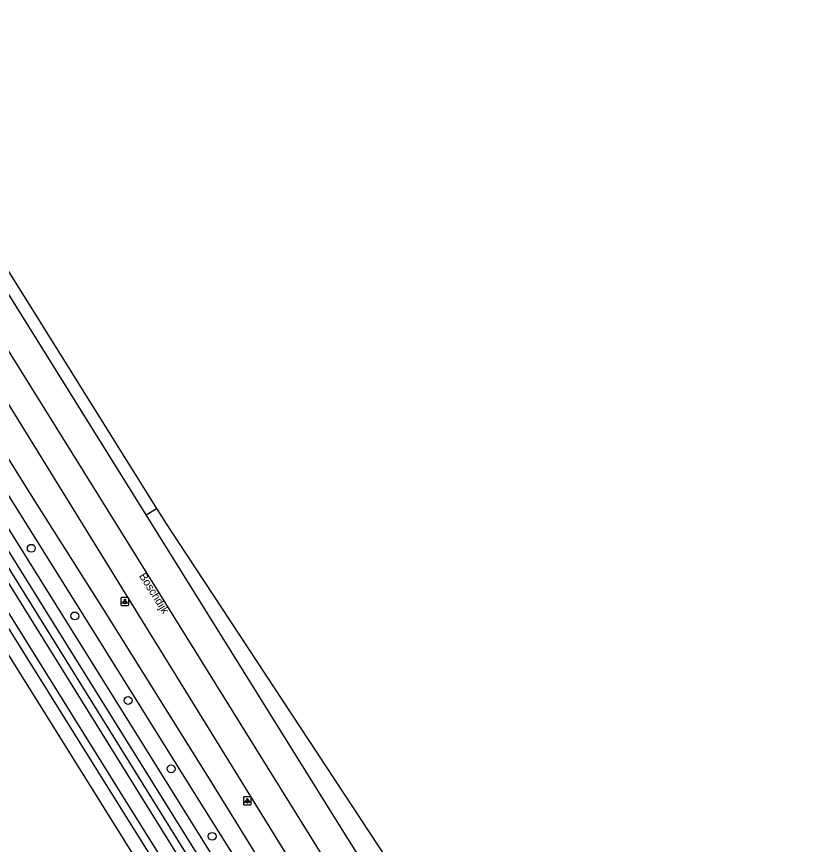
# Model space of a CAD drawing. Extents: x 158132 to 159658, y 385257 to 387209.
# Drawn here: x 159042.6 to 159140.1, y 386809.7 to 386913.1 of the extents above; entities that cross this region are included whole.
import ezdxf

# ---------------------------------------------------------------- set-up
doc = ezdxf.new("R2010")
doc.units = 0
for name, color, linetype in [('IMGEO_Boom', 7, 'Continuous'), ('IMGEO_Fietspad_gesloten', 7, 'Continuous'), ('IMGEO_Gemengd_bos', 7, 'Continuous'), ('IMGEO_Hek', 7, 'Continuous'), ('IMGEO_Lichtpunt', 7, 'Continuous'), ('IMGEO_Openbare_ruimte_label', 7, 'Continuous'), ('IMGEO_Rijbaan_regionaal_gesloten', 7, 'Continuous'), ('IMGEO_Verkeerseiland_open', 7, 'Continuous'), ('IMGEO_Voetpad_open', 7, 'Continuous'), ('IMGEO_Waterloop', 7, 'Continuous')]:
    doc.layers.add(name, color=color, linetype=linetype)

msp = doc.modelspace()

# ---------------------------------------------------------------- linework, layer by layer
at = {"layer": 'IMGEO_Boom'}
for centre in [(159044.4, 386846.72), (159049.84, 386838.27), (159056.5, 386827.71), (159061.88, 386819.16), (159067.01, 386810.74)]:
    msp.add_circle(centre, 0.489, dxfattribs=at)
at = {"layer": 'IMGEO_Fietspad_gesloten'}
for points in [[(158941.33, 387013.3), (158945.18, 387007.28), (158949.85, 387000), (158956.19, 386989.91), (158968.82, 386969.55), (158983.07, 386946.51), (158996.04, 386925.89), (159000, 386919.62), (159009.4, 386904.75), (159021.52, 386885.26), (159031.61, 386869.16), (159043.05, 386850.88), (159051.47, 386837.43), (159064.7, 386816.23), (159071.45, 386805.45), (159075.09, 386799.57), (159078.06, 386794.8)], [(159116.57, 386729), (159103.46, 386750), (159087.41, 386775.7), (159087.28, 386775.92), (159086.31, 386777.79), (159085.51, 386779.75), (159084.88, 386781.77), (159082.05, 386791.86), (159081.53, 386793.42), (159080.87, 386794.93), (159080.27, 386796.04), (159077.25, 386800.87), (159073.57, 386806.72), (159067, 386817.36), (159053.63, 386838.77), (159044.62, 386852.96), (159033.41, 386870.98), (159019.9, 386892.6), (159007.98, 386911.66), (159000, 386924.5)]]:
    msp.add_lwpolyline(points, dxfattribs=at)
at = {"layer": 'IMGEO_Gemengd_bos'}
for points in [[(158949.71, 386982.58), (158967.97, 386954.01), (158977.45, 386938.63), (158982.43, 386931.1), (158988.76, 386921.08), (159000, 386903.6), (159031.24, 386853.2), (159055.81, 386813.89), (159067.59, 386795.06), (159071.31, 386789.11), (159074.93, 386782.92), (159078.25, 386775.14), (159080.08, 386771.7)], [(159113.76, 386724.1), (159103.03, 386741.54), (159098.78, 386748.57), (159097.88, 386750), (159086.96, 386767.29), (159084.19, 386772.04), (159081.92, 386776.26), (159079.98, 386780.79), (159078.46, 386784.25), (159076.71, 386787.6), (159070.91, 386797.06), (159068.85, 386800.41), (159000, 386911.16), (158992.15, 386923.2)]]:
    msp.add_lwpolyline(points, dxfattribs=at)
at = {"layer": 'IMGEO_Hek'}
msp.add_lwpolyline([(159000, 386899.91), (159066.06, 386794.15)], dxfattribs=at)
at = {"layer": 'IMGEO_Lichtpunt'}
for p, q in [((159055.6, 386840.47), (159055.6, 386839.66)), ((159055.6, 386840.47), (159055.6, 386839.66)), ((159056.5, 386840.57), (159055.69, 386840.57)), ((159056.5, 386840.57), (159055.69, 386840.57)), ((159056.59, 386839.66), (159056.59, 386840.47)), ((159056.59, 386839.66), (159056.59, 386840.47)), ((159055.69, 386839.57), (159056.5, 386839.57)), ((159055.69, 386839.57), (159056.5, 386839.57)), ((159070.9, 386815.57), (159070.9, 386814.77)), ((159070.9, 386815.57), (159070.9, 386814.77)), ((159071.8, 386815.67), (159070.99, 386815.67)), ((159071.8, 386815.67), (159070.99, 386815.67)), ((159071.89, 386814.77), (159071.89, 386815.57)), ((159071.89, 386814.77), (159071.89, 386815.57)), ((159070.99, 386814.67), (159071.8, 386814.67)), ((159070.99, 386814.67), (159071.8, 386814.67))]:
    msp.add_line(p, q, dxfattribs=at)
for points in [[(159055.97, 386840.13), (159056.01, 386840.11), (159055.82, 386839.84), (159055.78, 386839.87), (159055.97, 386840.13)], [(159056.07, 386840.09), (159056.12, 386840.09), (159056.12, 386839.76), (159056.07, 386839.76), (159056.07, 386840.09)], [(159056.18, 386840.11), (159056.22, 386840.13), (159056.41, 386839.87), (159056.37, 386839.84), (159056.18, 386840.11)], [(159071.27, 386815.24), (159071.31, 386815.21), (159071.12, 386814.95), (159071.08, 386814.97), (159071.27, 386815.24)], [(159071.37, 386815.19), (159071.42, 386815.19), (159071.42, 386814.87), (159071.37, 386814.87), (159071.37, 386815.19)], [(159071.48, 386815.21), (159071.52, 386815.24), (159071.71, 386814.97), (159071.67, 386814.95), (159071.48, 386815.21)]]:
    msp.add_lwpolyline(points, dxfattribs=at)
for centre in [(159056.1, 386840.27), (159071.4, 386815.37)]:
    msp.add_circle(centre, 0.0994, dxfattribs=at)
for centre, start, end in [((159055.69, 386840.47), 90, 180), ((159055.69, 386840.47), 90, 180), ((159056.5, 386840.47), 0, 90), ((159056.5, 386840.47), 0, 90), ((159055.69, 386839.66), 180, 270), ((159055.69, 386839.66), 180, 270), ((159056.5, 386839.66), 270, 0), ((159056.5, 386839.66), 270, 360), ((159070.99, 386815.57), 90, 180), ((159070.99, 386815.57), 90, 180), ((159071.8, 386815.57), 0, 90), ((159071.8, 386815.57), 0, 90), ((159070.99, 386814.77), 180, 270), ((159070.99, 386814.77), 180, 270), ((159071.8, 386814.77), 270, 0), ((159071.8, 386814.77), 270, 360)]:
    msp.add_arc(centre, 0.0946, start, end, dxfattribs=at)
at = {"layer": 'IMGEO_Rijbaan_regionaal_gesloten'}
for points in [[(159132.72, 386721.99), (159125.95, 386732.99), (159118.54, 386745.29), (159113.12, 386754.13), (159106.44, 386765.8), (159097.37, 386781.66), (159076.66, 386814.97), (159052.05, 386854.56), (159019.18, 386907.28), (159008.52, 386924.33), (158987.11, 386958.55), (158967.99, 386989.3), (158948.87, 387020.05), (158922.43, 387060.66), (158915.85, 387070.53), (158892.84, 387103.79), (158867.82, 387140.66), (158850.57, 387167.06), (158841.17, 387181.88)], [(159058.74, 386850.89), (159039.3, 386882.04), (159024.03, 386906.51), (159004.62, 386937.46), (159000, 386944.85), (158989.71, 386961.33), (158975.98, 386983.29), (158965.55, 387000), (158956.04, 387014.92), (158952.62, 387020.3), (158942.06, 387036.92), (158934.41, 387048.85), (158932.01, 387052.45), (158927.86, 387058.82), (158924.52, 387063.91), (158921.65, 387068.35), (158918.5, 387073.22), (158916.22, 387076.6)], [(158937.06, 387048.69), (158937.81, 387047.54), (158938.99, 387045.64), (158941.49, 387041.35), (158949.18, 387028.98), (158954.02, 387021.18), (158956.71, 387016.86), (158965.07, 387003.5), (158967.35, 387000), (158978.52, 386982.01), (159000, 386947.66), (159016.97, 386920.42), (159031.34, 386897.46), (159040.61, 386882.82), (159060.03, 386851.7)], [(158933.03, 387037.86), (158938.97, 387028.57), (158944.43, 387020), (158946.6, 387016.58), (158951.09, 387009.51), (158957.04, 387000), (158971.62, 386976.38), (158987.66, 386950.66), (159000, 386930.88), (159006.31, 386920.77), (159012.93, 386910.23), (159024.95, 386891.53), (159076.51, 386808.08), (159079.97, 386802.5), (159097.62, 386774.07)], [(159060.03, 386851.7), (159061.67, 386849.16), (159088.88, 386807.86), (159097.59, 386794.63), (159098.72, 386792.91), (159104.7, 386783.36), (159116.43, 386764.6), (159125.54, 386750), (159140.14, 386726.61)], [(159100.94, 386783.31), (159086.49, 386806.42), (159083.26, 386811.59), (159058.74, 386850.89)]]:
    msp.add_lwpolyline(points, dxfattribs=at)
at = {"layer": 'IMGEO_Verkeerseiland_open'}
msp.add_lwpolyline([(159058.74, 386850.89), (159060.03, 386851.7)], dxfattribs=at)
at = {"layer": 'IMGEO_Voetpad_open'}
for points in [[(159081.94, 386783.14), (159081.37, 386784.78), (159080.78, 386786.08), (159076.42, 386793.24), (159073.19, 386798.43), (159014.42, 386892.71), (158939.72, 387012.31)], [(158938.43, 387011.51), (159013.13, 386891.92), (159071.89, 386797.65), (159074.97, 386792.72), (159079.55, 386785.11), (159080.16, 386783.63), (159080.65, 386782.05), (159081.64, 386778.91), (159082.91, 386775.86), (159083.96, 386773.8), (159098.83, 386750), (159121.59, 386713.58)]]:
    msp.add_lwpolyline(points, dxfattribs=at)
at = {"layer": 'IMGEO_Waterloop'}
for points in [[(158991.28, 386922.63), (158999.12, 386910.6), (159067.96, 386799.86), (159070.02, 386796.51), (159075.8, 386787.08), (159077.52, 386783.79), (159079.03, 386780.37), (159080.98, 386775.81), (159083.28, 386771.53), (159086.07, 386766.75), (159097, 386749.44), (159097.89, 386748.03), (159102.14, 386741), (159112.65, 386723.36)], [(159111.51, 386722.6), (159100.89, 386740.23), (159096.36, 386747.02), (159094.08, 386750.57), (159085.13, 386764.45), (159081, 386772.19), (159079.19, 386775.59), (159075.87, 386783.39), (159072.21, 386789.65), (159068.47, 386795.61), (159056.69, 386814.44), (159032.13, 386853.75), (159000.88, 386904.15), (158989.64, 386921.64)]]:
    msp.add_lwpolyline(points, dxfattribs=at)

# ---------------------------------------------------------------- texts
at = {"layer": 'IMGEO_Openbare_ruimte_label'}
msp.add_text('Boschdijk', height=1, rotation=302.0539, dxfattribs=at).set_placement((159057.83, 386843.27))

doc.saveas('drawing.dxf')
